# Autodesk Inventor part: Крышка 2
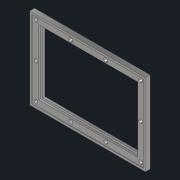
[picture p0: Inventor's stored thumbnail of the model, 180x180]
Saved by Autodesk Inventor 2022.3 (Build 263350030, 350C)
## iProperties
Created: 2022-08
Part Number: Крышка 2
Material: Сталь 40ХНМА
Document SubType Name: Modeling
Designer: Карташов
Density: 7.85 g/cm^3
Appearance: С умеренной полировкой
Author: Карташов
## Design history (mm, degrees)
sketch "Эскиз1"
  geometry: L1 (-85, -60)-(85, -60); L2 (85, -60)-(85, 60); L3 (85, 60)-(-85, 60); L4 (-85, 60)-(-85, -60); L5 (-85, -60)-(85, 60); L6 (85, -60)-(-85, 60); L7 (-70, -45)-(70, -45); L8 (70, -45)-(70, 45); L9 (70, 45)-(-70, 45); L10 (-70, 45)-(-70, -45); L11 (-70, -45)-(70, 45); L12 (70, -45)-(-70, 45); 1 further point
  constraints: 24 end point, 4 midpoint, 4 parallel, 2 horizontal, 2 perpendicular
  dimensions: "d0" = 170 distance of L3.end L2.end; "d1" = 120 distance of L2.end L1.end; "d2" = 140 distance of L9.end L8.end; "d3" = 90 distance of L8.end L7.end
extrude "Выдавливание1" new body sketch "Эскиз1" distance "d4" = 7; taper "d5" = 0 deg
sketch "Эскиз2"
  geometry: L1 (85, -60)-(85, 60) reference; L2 (85, 60)-(-85, 60) reference; L3 (-85, 60)-(-85, -60) reference; L4 (-85, -60)-(85, -60) reference; L5 (-70, -45)-(-70, 45) reference; L6 (-70, 45)-(70, 45) reference; L7 (70, 45)-(70, -45) reference; L8 (70, -45)-(-70, -45) reference; L9 (-82, -57)-(82, -57); L10 (82, -57)-(82, 57); L11 (82, 57)-(-82, 57); L12 (-82, 57)-(-82, -57); L13 (-82, -57)-(82, 57); L14 (82, -57)-(-82, 57); 2 further points
  constraints: 12 end point, 3 midpoint, 2 parallel, 1 horizontal, 1 perpendicular
  dimensions: "d6" = 57 distance from line of point (0, 0) L9; "d7" = 3 distance between parallel lines of L1 L10
extrude "Выдавливание2" cut sketch "Эскиз2" distance "d8" = 1; taper "d9" = 0 deg
sketch "Эскиз3"
  geometry: L1 (-73, 48)-(73, 48); L2 (73, 48)-(73, -48); L3 (73, -48)-(-73, -48); L4 (-73, -48)-(-73, 48); L5 (-73, 48)-(73, -48); L6 (73, 48)-(-73, -48); L7 (85, -60)-(85, 60) reference; 2 further points
  constraints: 12 end point, 3 midpoint, 2 parallel, 1 horizontal, 1 perpendicular
  dimensions: "d10" = 48 distance from line of point (0, 0) L3; "d11" = 12 distance between parallel lines of L2 L7
extrude "Выдавливание3" cut sketch "Эскиз3" distance "d12" = 3; taper "d13" = 0 deg
sketch "Эскиз4"
  geometry: L1 (-85, -60)-(-85, 60) reference; L2 (85, -60)-(-85, -60) reference; L3 (85, 60)-(85, -60) reference; L4 (-85, 60)-(85, 60) reference; L5 (70, -45)-(70, 45) reference; L6 (-70, -45)-(70, -45) reference; L7 (-70, 45)-(-70, -45) reference; L8 (70, 45)-(-70, 45) reference; 5 further points
  constraints: 2 horizontal alignment, 1 midpoint, 1 vertical alignment
  dimensions: "d14" = 77 horizontal distance of point (0, 0) point (-77, 52); "d15" = 52 vertical distance of point (0, 0) point (-77, 52); "d16" = 25.665 horizontal distance of point (0, 0) point (-25.665, 52)
hole "Отверстие1" sketch "Эскиз4" at (-77, 52), (-25.665, 52), (-77, 0) diameter "d17" = 6; stored, may be unused: countersink angle "d21" = 90 deg, drill point angle "d23" = 0 deg; dims "d18" = 6, "d19" = 10, "d20" = 2, "d22" = 22.5
mirror "Зеркальное отражение1"
mirror "Зеркальное отражение2"
node "Твердое тело1"
node "Спроецированная петля1"
node "Спроецированная петля2"
